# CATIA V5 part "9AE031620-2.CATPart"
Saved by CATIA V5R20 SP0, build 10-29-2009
Part number: 9AE031620-2
Revision: ANY
Definition: UNKNOWN
Nomenclature: 9AE031620-2
Source: Unknown
Bounding box of the stored display mesh (mm): x -11 to 11, y -10.833 to 10.833, z 0 to 32
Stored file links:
  C:\Users\Utente\Desktop\IO LAVORO\3D X SITO CF\CUMSA\3D files AE\AE 031620\9AE031620-2.CATPart
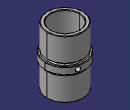
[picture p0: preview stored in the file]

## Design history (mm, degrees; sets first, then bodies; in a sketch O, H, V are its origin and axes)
Body1 "Cortar-Extruir2" (main body)
  Solid1: solid without history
